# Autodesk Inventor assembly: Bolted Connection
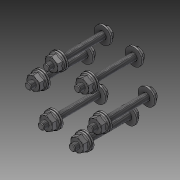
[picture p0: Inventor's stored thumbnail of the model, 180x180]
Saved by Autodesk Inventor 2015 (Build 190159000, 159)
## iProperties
Created: 2015-01
Part Number: Bolted Connection
Document SubType Name: Assembly
Designer: TODD D MILLER
Mass: 78.5896 g
Surface Area: 111.342 cm^2
Volume: 10.0114 cm^3
Density: 7.85 g/cm^3
ClientObjectVersion: 1
Author: TODD D MILLER
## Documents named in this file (4)
- C:\Users\TODD D MILLER\OneDrive\TCM Design Group\FIRST\CAD Library\Mecanum wheels\6-mecanum-3-Left with HUB\Design Accelerator\Bolted Connection1.iam
- C:\Users\TODD D MILLER\Documents\Inventor\Content Center Files\R2015\en-US\ANSI B18.22.1\ANSI B18.22.1 - No. 10 - Type A.ipt
- C:\Users\TODD D MILLER\Documents\Inventor\Content Center Files\R2015\en-US\ANSI B18.6.3(40)\ANSI B18.6.3 - 10-32 UNF x 1.75(6).ipt
- C:\Users\TODD D MILLER\Documents\Inventor\Content Center Files\R2015\en-US\IFI (1)\IFI - I0.19 - 32(1).ipt
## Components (24 placed, 3 different names)
1. Plain Washer (Inch) No. 10 - Type A:1
2. Plain Hex Head Machine Screw - Inch 10-32 UNF x 1.75:1
3. Plain Washer (Inch) No. 10 - Type A:2
4. Hex Flange Nut - Inch (IFI) I0.19 - 32:1
5. Plain Hex Head Machine Screw - Inch 10-32 UNF x 1.75:2
6. Plain Hex Head Machine Screw - Inch 10-32 UNF x 1.75:3
7. Plain Hex Head Machine Screw - Inch 10-32 UNF x 1.75:4
8. Plain Hex Head Machine Screw - Inch 10-32 UNF x 1.75:5
9. Plain Hex Head Machine Screw - Inch 10-32 UNF x 1.75:6
10. Plain Washer (Inch) No. 10 - Type A:3
11. Plain Washer (Inch) No. 10 - Type A:4
12. Plain Washer (Inch) No. 10 - Type A:5
13. Plain Washer (Inch) No. 10 - Type A:6
14. Plain Washer (Inch) No. 10 - Type A:7
15. Plain Washer (Inch) No. 10 - Type A:8
16. Plain Washer (Inch) No. 10 - Type A:9
17. Plain Washer (Inch) No. 10 - Type A:10
18. Plain Washer (Inch) No. 10 - Type A:11
19. Plain Washer (Inch) No. 10 - Type A:12
20. Hex Flange Nut - Inch (IFI) I0.19 - 32:2
21. Hex Flange Nut - Inch (IFI) I0.19 - 32:3
22. Hex Flange Nut - Inch (IFI) I0.19 - 32:4
23. Hex Flange Nut - Inch (IFI) I0.19 - 32:5
24. Hex Flange Nut - Inch (IFI) I0.19 - 32:6
